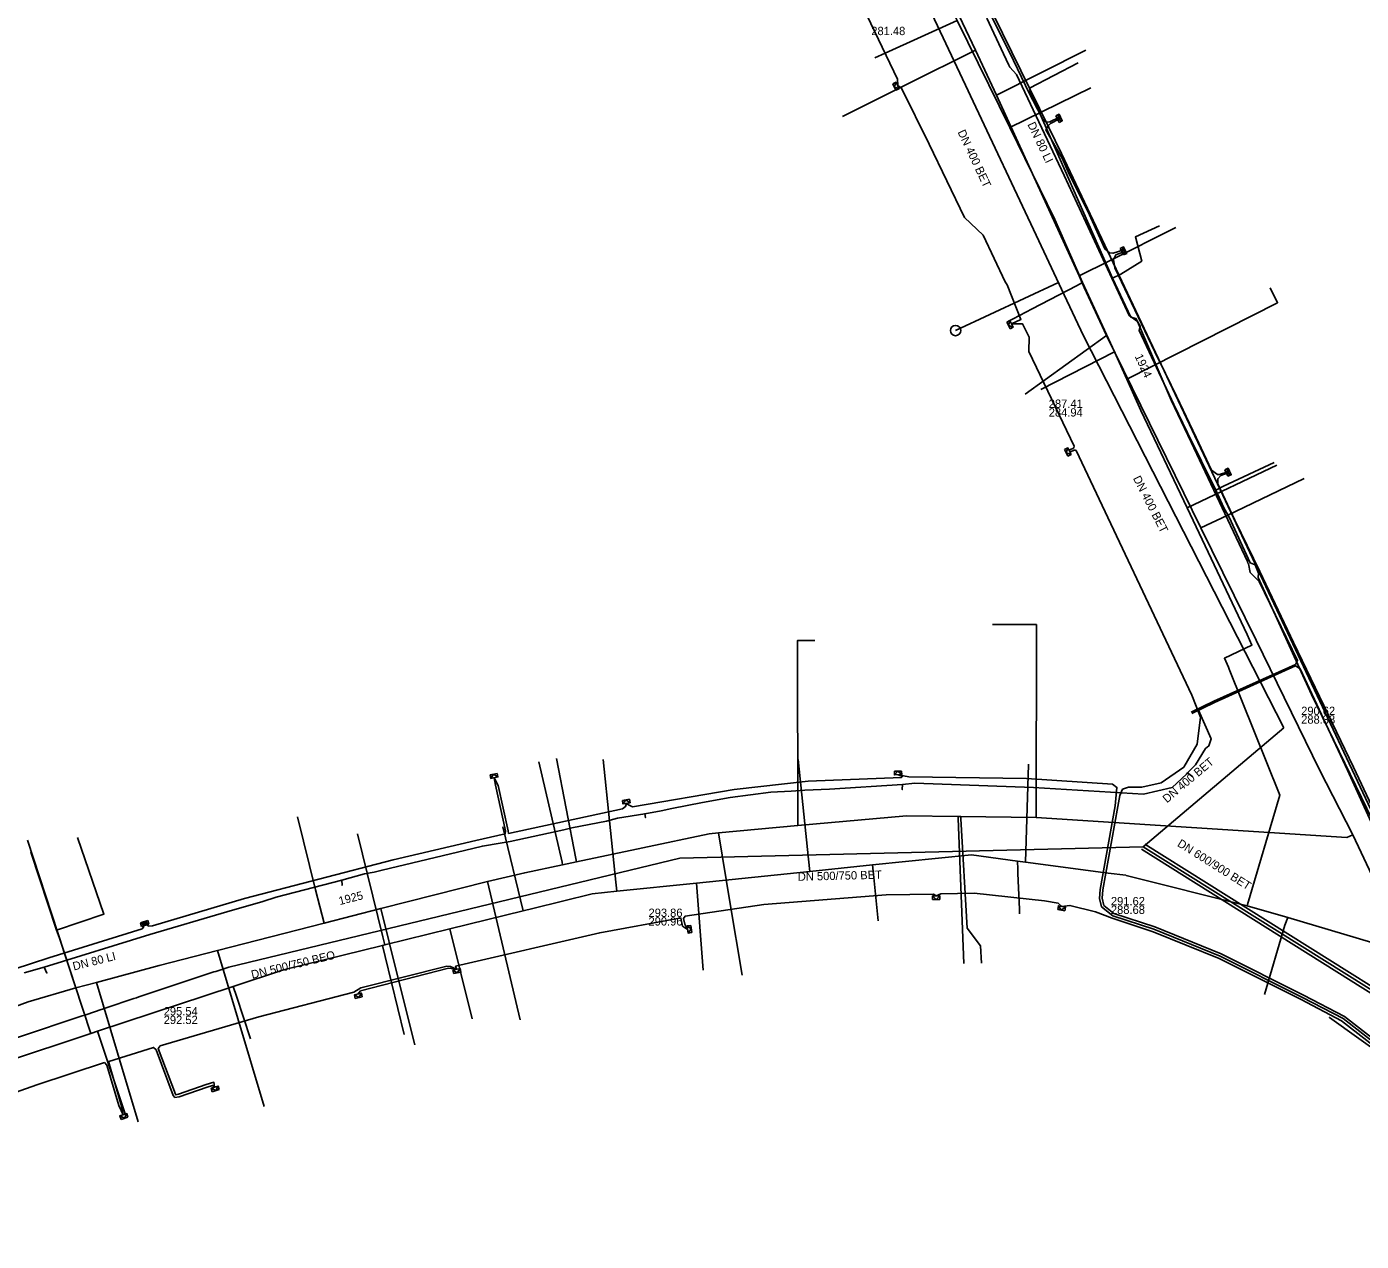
# Model space of a CAD drawing. Extents: x -600391 to -599491, y -1160176 to -1159402.
# Drawn here: x -600165.1 to -600036.7, y -1159664.8 to -1159547.9 of the extents above; entities that cross this region are included whole.
import ezdxf

# ---------------------------------------------------------------- set-up
doc = ezdxf.new("R2010")
doc.units = 0
for name, color, linetype in [('28', 7, 'Continuous'), ('31', 7, 'Continuous'), ('UPC_ok_linie', 7, 'Continuous'), ('Vrstva 10', 7, 'Continuous'), ('Vrstva 11', 7, 'Continuous'), ('Vrstva 12', 7, 'Continuous'), ('Vrstva 13', 7, 'Continuous'), ('Vrstva 15', 7, 'Continuous'), ('Vrstva 16', 7, 'Continuous'), ('Vrstva 42', 7, 'Continuous'), ('Vrstva 43', 7, 'Continuous'), ('Vrstva 55', 7, 'Continuous'), ('Vrstva 9', 7, 'Continuous')]:
    doc.layers.add(name, color=color, linetype=linetype)

# ---------------------------------------------------------------- blocks, each defined once
blk = doc.blocks.new('NN630')
at = {"layer": '31'}
for points in [[(0, -0.7), (-0.7, 0)], [(-0.7, -0.7), (-0.7, 0), (0.7, 0), (0.7, -0.7)], [(-0.7, -0.7), (0.7, -0.7)], [(0, -0.7), (0.7, 0)]]:
    blk.add_lwpolyline(points, dxfattribs=at)
blk = doc.blocks.new('NN620')
at = {"layer": '28'}
for points in [[(0.75, 0), (-0.75, 0)], [(-0.75, 0), (-0.75, -0.75)], [(0.75, -0.75), (0.75, 0)], [(-0.75, -0.75), (0.75, -0.75)], [(0.37, -0.18), (-0.38, -0.18)], [(-0.38, -0.18), (-0.38, -0.56)], [(-0.38, -0.56), (0.37, -0.56)], [(0.32, -0.23), (-0.33, -0.23)], [(-0.33, -0.23), (-0.33, -0.51)], [(-0.33, -0.51), (0.32, -0.51)], [(0.27, -0.27), (-0.28, -0.27)], [(-0.28, -0.27), (-0.28, -0.46)], [(-0.28, -0.46), (0.27, -0.46)], [(0.23, -0.32), (-0.23, -0.32)], [(-0.23, -0.32), (-0.23, -0.42)], [(-0.23, -0.42), (0.23, -0.42)], [(-0.19, -0.37), (0.19, -0.37)], [(0.23, -0.42), (0.23, -0.32)], [(0.27, -0.46), (0.27, -0.27)], [(0.32, -0.51), (0.32, -0.23)], [(0.37, -0.56), (0.37, -0.18)]]:
    blk.add_lwpolyline(points, dxfattribs=at)

msp = doc.modelspace()

# ---------------------------------------------------------------- linework, layer by layer
at = {"layer": 'UPC_ok_linie'}
for points in [[(-600068.65, -1159553.84), (-600063.97, -1159551.39)], [(-600034.04, -1159627.56), (-600041.51, -1159612.19), (-600046.65, -1159600.93), (-600046.6, -1159600.5), (-600046.93, -1159599.71), (-600047.42, -1159599.51), (-600049.45, -1159595.11), (-600049.94, -1159594.21), (-600050.71, -1159592.52), (-600053.43, -1159587), (-600054.76, -1159584.26), (-600058.09, -1159577.15), (-600058, -1159576.72), (-600058.41, -1159575.99), (-600058.88, -1159575.86), (-600060.66, -1159572.11), (-600068.57, -1159554.14), (-600068.65, -1159553.84)], [(-600060.66, -1159572.11), (-600059.87, -1159571.73), (-600057.85, -1159570.49), (-600058.46, -1159568.14), (-600056.14, -1159567.08)], [(-600050.71, -1159592.52), (-600049.97, -1159592.13), (-600045.1, -1159589.84)]]:
    msp.add_lwpolyline(points, dxfattribs=at)
at = {"layer": 'Vrstva 10'}
for p, q in [((-600057.87, -1159627.07), (-600020.19, -1159650.74)), ((-600057.55, -1159626.57), (-600019.87, -1159650.24))]:
    msp.add_line(p, q, dxfattribs=at)
at = {"layer": 'Vrstva 11'}
msp.add_circle((-600075.75, -1159577.15), 0.5, dxfattribs=at)
at = {"layer": 'Vrstva 13'}
for p, q in [((-600071.8, -1159554.49), (-600063.21, -1159550.18)), ((-600061.25, -1159577.63), (-600069.06, -1159583.27)), ((-600037.54, -1159625.67), (-600037.82, -1159625.82)), ((-600160.36, -1159640.42), (-600165.02, -1159626.2)), ((-600120.76, -1159630.18), (-600117.63, -1159643.48))]:
    msp.add_line(p, q, dxfattribs=at)
for points in [[(-600046.85, -1159606.94), (-600052.15, -1159596.14), (-600061.25, -1159577.63), (-600063.38, -1159573), (-600063.87, -1159571.88), (-600065.76, -1159567.75), (-600071.8, -1159554.49), (-600073.85, -1159550.16), (-600082.21, -1159532.51)], [(-600073.85, -1159550.16), (-600080.4, -1159553.44), (-600086.62, -1159556.56)], [(-600063.87, -1159571.88), (-600060.95, -1159570.43), (-600054.57, -1159567.25)], [(-600052.15, -1159596.14), (-600049.63, -1159594.95), (-600042.23, -1159591.4)], [(-600068, -1159624.02), (-600067.98, -1159605.45), (-600072.21, -1159605.45)], [(-600090.94, -1159624.79), (-600090.96, -1159606.99), (-600089.29, -1159606.99)], [(-600037.54, -1159625.67), (-600040.74, -1159619.42), (-600046.85, -1159606.94)], [(-600112.21, -1159628.27), (-600112.27, -1159627.95), (-600114.15, -1159618.32)], [(-600113.55, -1159628.56), (-600113.6, -1159628.3), (-600115.83, -1159618.65)], [(-600037.82, -1159625.82), (-600038.13, -1159625.95), (-600068, -1159624.02), (-600075.25, -1159623.91), (-600075.5, -1159623.91), (-600080.47, -1159623.84), (-600090.94, -1159624.79), (-600098.55, -1159625.5), (-600099.46, -1159625.59), (-600112.21, -1159628.27), (-600113.55, -1159628.56), (-600117.19, -1159629.33), (-600120.76, -1159630.18), (-600131.05, -1159632.78), (-600136.5, -1159634.18), (-600146.76, -1159636.81), (-600152.36, -1159638.24), (-600158.39, -1159639.89), (-600160.36, -1159640.42), (-600164.96, -1159641.74), (-600177.26, -1159646.28), (-600183.75, -1159648.7), (-600192.74, -1159652.02)], [(-600136.5, -1159634.18), (-600137.31, -1159630.98), (-600139.06, -1159623.94)], [(-600075.5, -1159623.91), (-600075.5, -1159624.12), (-600074.96, -1159638.07)], [(-600075.25, -1159623.91), (-600075.25, -1159624.14), (-600074.63, -1159634.67), (-600073.35, -1159636.35), (-600073.26, -1159638.04)], [(-600098.55, -1159625.5), (-600097.47, -1159632.13), (-600096.28, -1159639.19)], [(-600021.24, -1159642.75), (-600033.55, -1159634.11), (-600037.54, -1159625.67)], [(-600131.05, -1159632.78), (-600129.47, -1159639.11), (-600127.75, -1159645.89)], [(-600146.76, -1159636.81), (-600144.79, -1159643.36), (-600142.26, -1159651.82)], [(-600158.39, -1159639.89), (-600156.36, -1159646.65), (-600154.37, -1159653.31)]]:
    msp.add_lwpolyline(points, dxfattribs=at)
at = {"layer": 'Vrstva 16'}
for points in [[(-600049.5, -1159609.54), (-600049.9, -1159608.68), (-600047.24, -1159607.42), (-600047.72, -1159606.41), (-600053.49, -1159594.22), (-600057.92, -1159584.86), (-600059.29, -1159581.82), (-600060.47, -1159579.2), (-600063.54, -1159572.54), (-600066.19, -1159566.46), (-600070.53, -1159557.62), (-600075.61, -1159547.3), (-600076.73, -1159545.03), (-600083.53, -1159531.09), (-600089.79, -1159519.12), (-600089.81, -1159519.07), (-600095.09, -1159507), (-600096.81, -1159503.39), (-600097.75, -1159502.22)], [(-600075.61, -1159547.3), (-600082.51, -1159550.46)], [(-600082.51, -1159550.46), (-600083.52, -1159550.91)], [(-600070.53, -1159557.62), (-600062.75, -1159553.79)], [(-600070.81, -1159576.33), (-600068.37, -1159575.05), (-600064.12, -1159572.84), (-600063.54, -1159572.54)], [(-600059.29, -1159581.82), (-600044.78, -1159574.48), (-600045.5, -1159573.05)], [(-600067.56, -1159582.82), (-600060.47, -1159579.2)], [(-600053.49, -1159594.22), (-600044.85, -1159590.12)], [(-600013.42, -1159641.95), (-600019.54, -1159640.86), (-600043.8, -1159633.63), (-600047.71, -1159632.51), (-600047.67, -1159632.37), (-600044.57, -1159621.87), (-600049.42, -1159609.74), (-600049.5, -1159609.54)], [(-600109.66, -1159618.44), (-600108.44, -1159630.22), (-600108.35, -1159631.11)], [(-600090.88, -1159618.44), (-600089.9, -1159628.01), (-600089.77, -1159629.21)], [(-600069.02, -1159628.3), (-600068.73, -1159618.9), (-600068.73, -1159618.89)], [(-600162.22, -1159634.84), (-600157.67, -1159633.33), (-600160.22, -1159625.95)], [(-600133.28, -1159625.57), (-600130.84, -1159635.49), (-600130.65, -1159636.26)], [(-600117.35, -1159632.99), (-600119.29, -1159624.91)], [(-600162.22, -1159634.84), (-600164.71, -1159627.34)], [(-600059.38, -1159629.57), (-600061.07, -1159629.36), (-600069.02, -1159628.3), (-600069.8, -1159628.2), (-600074.23, -1159627.61), (-600083.74, -1159628.58), (-600089.77, -1159629.21), (-600100.67, -1159630.32), (-600108.35, -1159631.11), (-600110.71, -1159631.36), (-600116.41, -1159632.76), (-600117.35, -1159632.99), (-600124.39, -1159634.72), (-600130.65, -1159636.26), (-600130.89, -1159636.32), (-600140.41, -1159638.67), (-600145.24, -1159640.27), (-600158.28, -1159644.59), (-600158.92, -1159644.8), (-600175.67, -1159650.36), (-600180.54, -1159651.98), (-600187.8, -1159654.39), (-600192.98, -1159656.42), (-600214.42, -1159664.83)], [(-600083.19, -1159633.97), (-600083.62, -1159629.78), (-600083.74, -1159628.58)], [(-600069.61, -1159632.84), (-600069.75, -1159629.4), (-600069.77, -1159629), (-600069.8, -1159628.2)], [(-600047.71, -1159632.51), (-600059.35, -1159629.58), (-600059.38, -1159629.57)], [(-600100.67, -1159630.32), (-600100.04, -1159638.72)], [(-600069.6, -1159633.27), (-600069.61, -1159632.84)], [(-600043.8, -1159633.63), (-600044.09, -1159634.37)], [(-600158.92, -1159644.8), (-600161.99, -1159635.54), (-600162.22, -1159634.84)], [(-600124.39, -1159634.72), (-600122.26, -1159643.38)], [(-600044.09, -1159634.37), (-600046.03, -1159641.04)], [(-600128.79, -1159644.88), (-600130.63, -1159637.39), (-600130.89, -1159636.32)], [(-600143.57, -1159645.3), (-600144.93, -1159641.22), (-600145.24, -1159640.27)], [(-600158.28, -1159644.59), (-600155.61, -1159652.63)]]:
    msp.add_lwpolyline(points, dxfattribs=at)
at = {"layer": 'Vrstva 42'}
for points in [[(-600103.69, -1159520.99), (-600087.34, -1159515.52), (-600085.54, -1159519.37), (-600066.77, -1159557.61), (-600065.55, -1159560.1), (-600060.85, -1159570.09), (-600050.56, -1159591.91), (-600035.8, -1159623.24), (-600034.14, -1159626.98), (-600033.53, -1159628.07), (-600032.96, -1159627.91)], [(-600086.09, -1159543), (-600081.35, -1159552.96), (-600081.32, -1159553.57), (-600080.94, -1159553.82), (-600078.28, -1159559.2), (-600074.9, -1159566.28), (-600073.1, -1159567.97), (-600070.97, -1159572.46), (-600070.78, -1159572.76), (-600069.47, -1159576.1), (-600070.36, -1159576.5), (-600069.3, -1159576.52), (-600068.67, -1159577.79), (-600068.69, -1159579.16), (-600064.36, -1159588.29), (-600064.37, -1159588.4), (-600064.41, -1159588.47), (-600064.77, -1159588.63), (-600064.8, -1159588.76), (-600064.69, -1159588.82), (-600064.33, -1159588.65), (-600064.24, -1159588.66), (-600064.16, -1159588.71), (-600053.02, -1159612.24), (-600052.18, -1159614.36), (-600052.52, -1159616.96), (-600053.81, -1159619.16), (-600055.99, -1159620.68), (-600057.85, -1159621.08), (-600059.11, -1159621.1), (-600059.69, -1159621.3), (-600059.96, -1159621.9), (-600060.14, -1159622.95), (-600061.6, -1159630.98), (-600061.65, -1159631.78), (-600061.5, -1159632.48), (-600060.53, -1159633.24), (-600056.59, -1159634.53), (-600050.21, -1159637.12), (-600042.28, -1159641.1), (-600038.35, -1159643.15), (-600029.83, -1159649.78)], [(-600033.96, -1159626.67), (-600037.46, -1159619.18), (-600040.75, -1159612.36), (-600043.25, -1159607.16), (-600046.47, -1159600.34), (-600048.9, -1159595.4), (-600050.53, -1159591.9), (-600050.53, -1159591.41), (-600050.25, -1159591.1), (-600049.62, -1159590.86), (-600049.47, -1159590.82), (-600049.39, -1159590.71), (-600049.55, -1159590.7), (-600049.65, -1159590.77), (-600050.37, -1159591.02), (-600050.56, -1159591), (-600051.14, -1159590.59), (-600052.62, -1159587.45), (-600054.49, -1159583.47), (-600056.06, -1159580.23), (-600056.27, -1159579.87), (-600060.44, -1159571.11), (-600060.57, -1159570.3), (-600060.33, -1159569.88), (-600059.58, -1159569.57), (-600059.44, -1159569.41), (-600059.65, -1159569.43), (-600060.6, -1159569.72), (-600060.93, -1159569.66), (-600061.39, -1159569.3), (-600063.04, -1159565.67), (-600064.81, -1159562.09), (-600065.48, -1159560.62), (-600067.06, -1159557.85), (-600066.83, -1159557.44), (-600066.61, -1159557.23), (-600065.76, -1159556.77), (-600065.64, -1159556.65), (-600065.82, -1159556.65), (-600066.69, -1159557.06), (-600067.06, -1159557.11), (-600067.38, -1159556.77), (-600068.33, -1159554.98), (-600068.63, -1159554.37), (-600070.17, -1159551.16), (-600072.58, -1159546.31)], [(-600030.01, -1159649.96), (-600038.48, -1159643.36), (-600042.39, -1159641.32), (-600050.31, -1159637.35), (-600056.67, -1159634.77), (-600060.61, -1159633.48), (-600061.73, -1159632.6), (-600061.91, -1159631.8), (-600061.85, -1159630.94), (-600060.39, -1159622.9), (-600060.24, -1159621.11), (-600060.65, -1159620.81), (-600068.92, -1159620.25), (-600080.25, -1159620.09), (-600081.28, -1159619.9), (-600080.87, -1159620.06), (-600080.95, -1159620.16), (-600089.93, -1159620.52), (-600097.05, -1159621.32), (-600106.82, -1159622.98), (-600107.15, -1159622.84), (-600107.4, -1159622.65), (-600107.5, -1159622.96), (-600107.8, -1159623.17), (-600118.75, -1159625.55), (-600118.79, -1159625.3), (-600119.75, -1159620.92), (-600120.12, -1159620.18), (-600120.01, -1159620.91), (-600119.05, -1159625.31), (-600119.09, -1159625.6), (-600121.91, -1159626.23), (-600129.84, -1159628.09), (-600144.15, -1159631.8), (-600152.99, -1159634.45), (-600153.4, -1159634.47), (-600153.49, -1159634.35)], [(-600123.76, -1159638.62), (-600123.85, -1159638.33), (-600109.98, -1159635.11), (-600102.3, -1159633.69), (-600102.17, -1159633.69), (-600102.02, -1159634.46), (-600101.53, -1159634.79), (-600101.8, -1159634.29), (-600101.91, -1159633.74), (-600101.77, -1159633.52), (-600094.19, -1159632.39), (-600082.42, -1159631.46), (-600077.89, -1159631.38), (-600077.61, -1159631.56), (-600077.18, -1159631.35), (-600073.95, -1159631.31), (-600067.21, -1159632.02), (-600065.88, -1159632.26), (-600065.52, -1159632.58), (-600064.76, -1159632.48), (-600062.29, -1159633.09), (-600060.7, -1159633.71), (-600056.76, -1159635), (-600050.41, -1159637.57), (-600042.51, -1159641.54), (-600038.62, -1159643.58), (-600033.46, -1159647.59)], [(-600234.94, -1159654.13), (-600235.26, -1159654.09), (-600235.76, -1159654.29), (-600235.96, -1159654.62), (-600234.24, -1159657.27), (-600232.59, -1159659.07), (-600229.37, -1159660.89), (-600225.81, -1159660.96), (-600221.99, -1159659.71), (-600210.41, -1159655.07), (-600197.35, -1159649.76), (-600188.19, -1159646.13), (-600187.97, -1159645.84), (-600187.66, -1159645.84), (-600187.24, -1159645.85), (-600172.91, -1159640.77), (-600162.96, -1159637.52), (-600154, -1159634.74), (-600153.85, -1159634.56), (-600153.86, -1159634.46)], [(-600123.76, -1159638.62), (-600124.35, -1159638.36), (-600124.69, -1159638.32), (-600132.95, -1159640.41), (-600133.62, -1159640.82), (-600142.76, -1159643.2), (-600152.26, -1159645.97), (-600152.44, -1159646.24), (-600150.8, -1159650.64), (-600150.76, -1159650.69), (-600150.5, -1159650.65), (-600147.83, -1159649.71), (-600147.09, -1159649.49), (-600147.02, -1159649.96), (-600147.23, -1159649.79), (-600147.75, -1159649.95), (-600150.44, -1159650.9), (-600150.84, -1159650.95), (-600151.02, -1159650.78), (-600152.65, -1159646.38), (-600152.91, -1159646.14), (-600157.21, -1159647.5), (-600157.18, -1159647.72), (-600156.02, -1159651.65), (-600155.81, -1159652.62), (-600156.25, -1159651.73), (-600157.4, -1159647.84), (-600157.63, -1159647.6), (-600164.13, -1159649.73), (-600174.4, -1159653.35)], [(-600133.24, -1159641), (-600132.98, -1159640.7), (-600124.52, -1159638.51), (-600123.76, -1159638.62)]]:
    msp.add_lwpolyline(points, dxfattribs=at)
at = {"layer": 'Vrstva 55'}
for points in [[(-600053.1, -1159613.89), (-600050.9, -1159612.83), (-600043.07, -1159609.29), (-600042.86, -1159608.91), (-600046.56, -1159601.31), (-600047.41, -1159600.44), (-600047.56, -1159599.59), (-600047.65, -1159599.53), (-600047.67, -1159599.37), (-600053.08, -1159587.89), (-600055, -1159583.85), (-600058.25, -1159576.27), (-600059.05, -1159575.71), (-600065.31, -1159562.23), (-600069.88, -1159552.5), (-600070.52, -1159551.79), (-600070.64, -1159551.6), (-600071.15, -1159550.51), (-600072.73, -1159547.08)], [(-600053.04, -1159614), (-600050.84, -1159612.93), (-600043.06, -1159609.42), (-600042.62, -1159609.71), (-600038.06, -1159619.46), (-600034.51, -1159627.28), (-600033.74, -1159626.96), (-600033.62, -1159626.92), (-600033.66, -1159627.06), (-600034.45, -1159627.39), (-600032.94, -1159630.5), (-600030.94, -1159633.2), (-600028.46, -1159635.34), (-600025.63, -1159636.9), (-600023.53, -1159637.56), (-600023.07, -1159637.19), (-600022.82, -1159636.56)], [(-600053.07, -1159613.87), (-600052.7, -1159613.67), (-600052.37, -1159613.67), (-600051.16, -1159616.44), (-600051.38, -1159617.12), (-600051.7, -1159617.36), (-600052.66, -1159618.93), (-600053.44, -1159619.72), (-600052.94, -1159620.1), (-600053.44, -1159619.72), (-600053.55, -1159619.83), (-600054.92, -1159621.13), (-600057.68, -1159621.76), (-600068.27, -1159621.11), (-600079.67, -1159620.71), (-600080.87, -1159620.84), (-600080.88, -1159621.33), (-600080.87, -1159620.84), (-600087.88, -1159621.28), (-600090.26, -1159621.39), (-600091.57, -1159621.49), (-600093.52, -1159621.57), (-600097.43, -1159622.08), (-600100.11, -1159622.58), (-600103.04, -1159623.14), (-600104.08, -1159623.38), (-600105.65, -1159623.65), (-600105.59, -1159624.02), (-600105.65, -1159623.65), (-600108.27, -1159624.09), (-600109.32, -1159624.35), (-600112.66, -1159625), (-600113.42, -1159625.19), (-600118.6, -1159626.32), (-600119.56, -1159626.49), (-600121.27, -1159626.76), (-600122.2, -1159627), (-600130.91, -1159629.07), (-600131.69, -1159629.26), (-600132.62, -1159629.42), (-600134.8, -1159630.05), (-600134.77, -1159630.53), (-600134.8, -1159630.05), (-600141.09, -1159631.67), (-600142.38, -1159632.11), (-600145.86, -1159633.09), (-600153.24, -1159635.28), (-600163.42, -1159638.42), (-600163.16, -1159638.99), (-600163.42, -1159638.42), (-600165.34, -1159638.95)], [(-600022.71, -1159636.44), (-600023.16, -1159638.02), (-600023.22, -1159638.11), (-600023.37, -1159638.3), (-600030.31, -1159647.68), (-600031.32, -1159649.32), (-600039.8, -1159643.25), (-600031.32, -1159649.32), (-600023.73, -1159656.37), (-600020.64, -1159660.01), (-600017.34, -1159664.37), (-600017.03, -1159665.03)]]:
    msp.add_lwpolyline(points, dxfattribs=at)
at = {"layer": 'Vrstva 9'}
for p, q in [((-600065.86, -1159572.54), (-600075.75, -1159577.15)), ((-600057.71, -1159626.82), (-600044.17, -1159615.39)), ((-600102.28, -1159627.94), (-600057.71, -1159626.82)), ((-600057.71, -1159626.82), (-600020.03, -1159650.49)), ((-600145.67, -1159638.41), (-600102.28, -1159627.94))]:
    msp.add_line(p, q, dxfattribs=at)
for points in [[(-600063.45, -1159577.67), (-600065.31, -1159573.72), (-600068.01, -1159567.98), (-600074.31, -1159554.57), (-600074.54, -1159554.09), (-600078.02, -1159546.68), (-600080.35, -1159541.73)], [(-600044.17, -1159615.39), (-600052.35, -1159599.39), (-600063.45, -1159577.67)], [(-600172.03, -1159647.2), (-600159.76, -1159643.1), (-600159.51, -1159643.02), (-600159.32, -1159642.96), (-600157.95, -1159642.5), (-600157.82, -1159642.46), (-600157.47, -1159642.34), (-600154.78, -1159641.44), (-600154.55, -1159641.37), (-600154.3, -1159641.28), (-600147.19, -1159638.91), (-600147.09, -1159638.88), (-600146.9, -1159638.82), (-600145.67, -1159638.41)]]:
    msp.add_lwpolyline(points, dxfattribs=at)

# ---------------------------------------------------------------- block references
at = {"layer": 'Vrstva 43'}
for name, p, xscale, yscale, rotation in [('NN630', (-600081.33, -1159553.57), 0.5, 0.5, -66.00000000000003), ('NN630', (-600065.64, -1159556.65), 0.5000000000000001, 0.4999999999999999, -64), ('NN630', (-600059.44, -1159569.41), 0.5000000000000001, 0.4999999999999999, -64), ('NN630', (-600070.36, -1159576.5), 0.5, 0.5, -63.000000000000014), ('NN630', (-600064.8, -1159588.76), 0.5000000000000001, 0.4999999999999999, -64), ('NN630', (-600049.39, -1159590.71), 0.5000000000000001, 0.4999999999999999, -64), ('NN630', (-600081.28, -1159619.9), 0.5000000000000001, 0.4999999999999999, -178.00000000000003), ('NN630', (-600120.12, -1159620.18), 0.5000000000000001, 0.5, -169.00000000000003), ('NN630', (-600107.4, -1159622.65), 0.5, 0.5000000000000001, -170.00000000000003), ('NN630', (-600065.52, -1159632.58), 0.5000000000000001, 0.5, -10.999999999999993), ('NN620', (-600153.7, -1159634.39), 0.5, 0.5000000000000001, -163), ('NN630', (-600101.53, -1159634.79), 0.5000000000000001, 0.5, 98), ('NN630', (-600123.76, -1159638.62), 0.5, 0.5, 13), ('NN630', (-600133.24, -1159641), 0.49999999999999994, 0.5000000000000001, 14), ('NN630', (-600147.02, -1159649.96), 0.5, 0.5, 17.999999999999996), ('NN630', (-600155.81, -1159652.62), 0.5000000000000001, 0.5, 18.999999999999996)]:
    msp.add_blockref(name, p, dxfattribs=dict(at, xscale=xscale, yscale=yscale, rotation=rotation))
at = {"layer": 'Vrstva 43', "xscale": 0.5, "yscale": 0.5}
msp.add_blockref('NN630', (-600077.61, -1159631.56), dxfattribs=at)

# ---------------------------------------------------------------- texts
at = {"layer": 'Vrstva 12'}
for s, p in [('281.48', (-600083.86, -1159548.72)), ('287.41', (-600066.79, -1159584.59)), ('284.94', (-600066.79, -1159585.43)), ('290.62', (-600042.51, -1159614.15)), ('288.38', (-600042.51, -1159614.98)), ('291.62', (-600060.81, -1159632.46)), ('288.68', (-600060.81, -1159633.29)), ('293.86', (-600105.29, -1159633.58)), ('290.96', (-600105.29, -1159634.41)), ('295.54', (-600151.92, -1159643.06)), ('292.52', (-600151.92, -1159643.89))]:
    msp.add_text(s, height=0.8, dxfattribs=at).set_placement(p)
for s, rotation, p in [('DN 400 BET', 295.1879, (-600075.58, -1159558.05)), ('DN 400 BET', 297.0786, (-600058.71, -1159591.37)), ('DN 400 BET', 40.1643, (-600055.42, -1159622.66)), ('DN 600/900 BET', 327.7892, (-600054.49, -1159626.72)), ('DN 500/750 BET', 1.4439, (-600090.92, -1159630.11)), ('DN 500/750 BEO', 13.6567, (-600143.4, -1159639.54))]:
    msp.add_text(s, height=0.8, rotation=rotation, dxfattribs=at).set_placement(p)
at = {"layer": 'Vrstva 15'}
for s, rotation, p in [('DN 80 LI', 295.5316, (-600068.86, -1159557.31)), ('1924', 294.5003, (-600058.54, -1159579.62)), ('1925', 14.3812, (-600134.98, -1159632.45)), ('DN 80 LI', 14.3239, (-600160.56, -1159638.74))]:
    msp.add_text(s, height=0.8, rotation=rotation, dxfattribs=at).set_placement(p)

doc.saveas('drawing.dxf')
